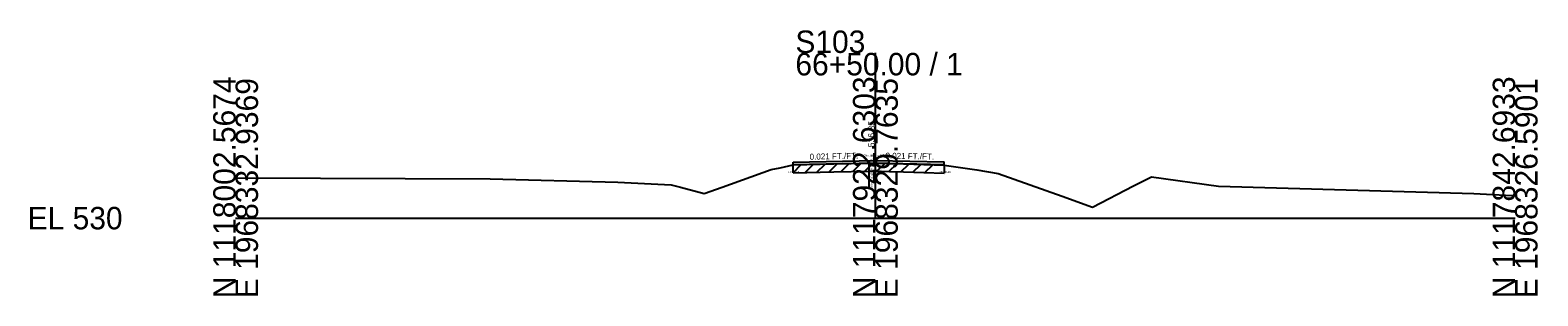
# Model space of a CAD drawing. Extents: x -26 to 163, y -10 to 24018.
# Drawn here: x -25.7 to 162.8, y 14490.3 to 14523.5 of the extents above; entities that cross this region are included whole.
import ezdxf

# ---------------------------------------------------------------- set-up
doc = ezdxf.new("R2010")
doc.units = 0
for name, color, linetype in [('RD_GPK_XS_Cell', 7, 'Continuous'), ('RD_XS_ExGround', 7, 'Continuous'), ('RD_XS_ExPaveRet', 7, 'Continuous'), ('RD_XS_Misc_Line', 7, 'Continuous'), ('RD_XS_PaveOvlay_CP', 7, 'Continuous'), ('RD_XS_TX_Elev_EX', 7, 'Continuous'), ('RD_XS_TX_ExEOP', 7, 'Continuous'), ('RD_XS_TX_Notes', 7, 'Continuous'), ('RD_XS_TX_Profile', 7, 'Continuous'), ('RD_XS_TX_Slope', 7, 'Continuous')]:
    doc.layers.add(name, color=color, linetype=linetype)

msp = doc.modelspace()

# ---------------------------------------------------------------- linework, layer by layer
at = {"layer": 'RD_GPK_XS_Cell'}
for p, q in [((80, 14500), (80, 14520.62)), ((0, 14500), (80, 14500)), ((80, 14500), (160, 14500))]:
    msp.add_line(p, q, dxfattribs=at)
at = {"layer": 'RD_XS_ExGround'}
msp.add_lwpolyline([(0, 14505.02), (31.85, 14504.92), (47.8, 14504.5), (54.48, 14504.17), (55.64, 14503.88), (58.61, 14503.08), (60.83, 14503.88), (66.97, 14506.09), (68.11, 14506.28), (69.7, 14506.65), (74.81, 14506.77), (79.18, 14506.87), (80, 14506.85), (83.5, 14506.76), (88.62, 14506.63), (92.68, 14506.01), (95.34, 14505.59), (103.37, 14502.74), (107.13, 14501.36), (112.29, 14504.05), (114.51, 14505.14), (122.9, 14503.98), (154.83, 14503.06), (159.6, 14502.82), (160, 14502.81)], dxfattribs=at)
at = {"layer": 'RD_XS_ExPaveRet'}
for p, q in [((69.7, 14505.65), (70.73, 14506.68)), ((69.7, 14505.65), (69.7, 14506.65)), ((69.7, 14505.65), (74.81, 14505.77)), ((71.2, 14505.69), (72.23, 14506.71)), ((72.7, 14505.72), (73.73, 14506.74)), ((74.2, 14505.75), (75.23, 14506.78)), ((74.81, 14505.77), (79.18, 14505.87)), ((75.7, 14505.79), (76.73, 14506.81)), ((77.2, 14505.83), (78.23, 14506.85)), ((78.7, 14505.86), (79.7, 14506.86)), ((79.18, 14505.87), (80, 14505.85)), ((80, 14505.85), (83.5, 14505.76)), ((80.2, 14505.85), (81.18, 14506.82)), ((81.7, 14505.81), (82.68, 14506.78)), ((83.2, 14505.77), (84.18, 14506.74)), ((83.5, 14505.76), (88.62, 14505.63)), ((84.7, 14505.73), (85.68, 14506.7)), ((86.2, 14505.69), (87.18, 14506.67)), ((88.62, 14506.63), (88.62, 14505.63))]:
    msp.add_line(p, q, dxfattribs=at)
at = {"layer": 'RD_XS_Misc_Line'}
msp.add_line((79.18, 14506.87), (79.18, 14503.87), dxfattribs=at)
at = {"layer": 'RD_XS_PaveOvlay_CP'}
for p, q in [((69.7, 14507), (80, 14507.21)), ((69.7, 14506.65), (69.7, 14507)), ((80, 14506.85), (69.7, 14506.64)), ((80, 14507.21), (88.62, 14507.03)), ((88.62, 14506.67), (80, 14506.85)), ((88.62, 14506.63), (88.62, 14507.03))]:
    msp.add_line(p, q, dxfattribs=at)

# ---------------------------------------------------------------- texts
at = {"layer": 'RD_GPK_XS_Cell'}
for s, p in [('S103', (70, 14520.62)), ('66+50.00 / 1', (70, 14517.82)), ('EL 530', (-26, 14498.6))]:
    msp.add_text(s, height=2.8, dxfattribs=at).set_placement(p)
for s, p in [('N 1118002.5674', (0, 14490)), ('E 1968332.9369', (2.8, 14490)), ('N 1117922.6303', (80, 14490)), ('E 1968329.7635', (82.8, 14490)), ('N 1117842.6933', (160, 14490)), ('E 1968326.5901', (162.8, 14490))]:
    msp.add_text(s, height=2.8, rotation=90, dxfattribs=at).set_placement(p)
at = {"layer": 'RD_XS_TX_Elev_EX'}
msp.add_text('536.85', height=0.8, rotation=90, dxfattribs=at).set_placement((79.9, 14508.85))
at = {"layer": 'RD_XS_TX_ExEOP'}
for s, p in [('EOP-L', (69.65, 14507)), ('EOP-R', (88.57, 14507.03))]:
    msp.add_text(s, height=0.1, rotation=270, dxfattribs=at).set_placement(p)
at = {"layer": 'RD_XS_TX_Notes'}
for s, p in [('Elev. @CL = 537.21', (78.49, 14507.71)), (' dE= 0.34', (68.99, 14505.65)), (' dE= 0.36', (79.29, 14505.85)), (' dE= 0.40', (87.91, 14505.63))]:
    msp.add_text(s, height=0.25, dxfattribs=at).set_placement(p)
msp.add_text(' Min. Distance @CP = -0.04', height=0.25, rotation=270, dxfattribs=at).set_placement((79.43, 14507.97))
at = {"layer": 'RD_XS_TX_Profile'}
msp.add_text('CL', height=0.25, dxfattribs=at).set_placement((79.77, 14507.21))
at = {"layer": 'RD_XS_TX_Slope'}
for rotation, p in [(1.1916, (71.79, 14507.29)), (358.8084, (81.26, 14507.43))]:
    msp.add_text('0.021 FT./FT.', height=0.75, rotation=rotation, dxfattribs=at).set_placement(p)

doc.saveas('drawing.dxf')
